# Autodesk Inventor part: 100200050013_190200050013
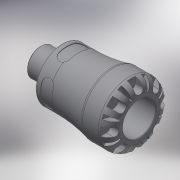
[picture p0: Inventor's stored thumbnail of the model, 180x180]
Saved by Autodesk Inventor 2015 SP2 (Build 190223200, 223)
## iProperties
Created: 2016-12
Part Number: 100200050013_190200050013
Material: Generic
Description: PLASSON MALE ADAPTOR 50X1.1/4" SERIES 1
Document SubType Name: Modeling
Designer: KIM
Mass: 447.839 g
Surface Area: 722.341 cm^2
Volume: 447.839 cm^3
Density: 1 g/cm^3
Appearance: Default
Author: KIM
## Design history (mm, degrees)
derived "1002.ipt"
feature "Solid1::1002.ipt"
tag "TaggingFeature1"
body "Solid1"
other parameters: "d0" = 122, "d1" = 32.76, "d3" = 62.5, "d4" = 85, "d6" = 78, "d8" = 72.25, "d13" = 9, "d14" = 9, "d15" = 0, "d17" = 360 deg, "d19" = 8 deg, "d20" = 1, "d21" = 1, "d22" = 8 deg, "d24" = 0, "d26" = 360 deg, "d32" = 0.925, "d33" = 8.5, "d34" = 41.91, "d38" = 21, "d39" = 1.2573, "d42" = 17.5, "d43" = 11.5, "d45" = 17.64, "d46" = 0, "d59" = 360 deg, "d61" = 14.875, "d62" = 1, "d64" = 0, "d65" = 0.85, "E_" = 85, "H_" = 122, "l_" = 78, "R_" = 41.91, "l_2" = 21, "d9" = 11.25, "d11" = 85, "d12" = 62.5
